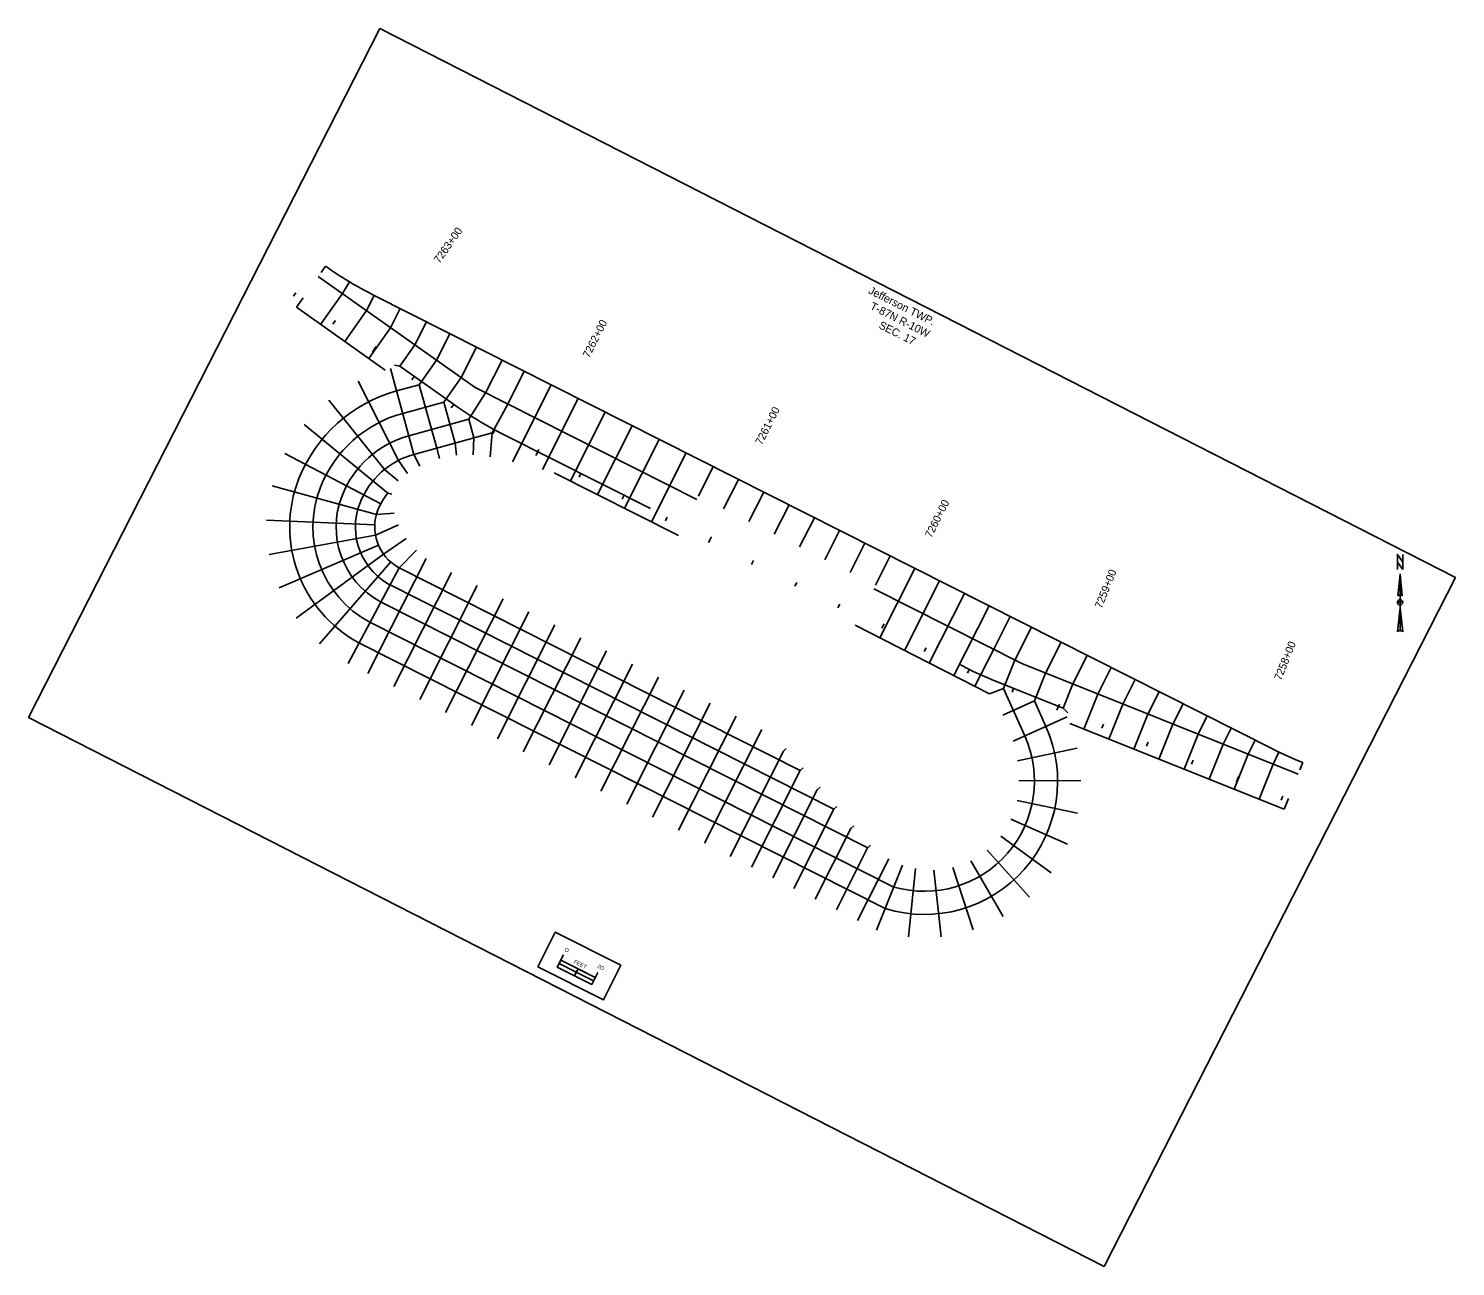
# Model space of a CAD drawing. Extents: x 15558113 to 15568216, y 8783175 to 8787996.
import ezdxf

# ---------------------------------------------------------------- set-up
doc = ezdxf.new("R2010")
doc.units = 0
for name, color, linetype in [('Draft_0', 7, 'Continuous'), ('Drainage', 7, 'Continuous'), ('dsnCellElements', 7, 'Continuous'), ('dsnCellsScaleBlock', 7, 'Continuous'), ('EdgeShoulder', 7, 'Continuous'), ('Miscellanous', 7, 'Continuous'), ('Text', 7, 'Continuous'), ('TextAlignment', 7, 'Continuous')]:
    doc.layers.add(name, color=color, linetype=linetype)

msp = doc.modelspace()

# ---------------------------------------------------------------- linework, layer by layer
at = {"layer": 'Drainage'}
for p, q in [((15558292.1, 8787830.96), (15558290.84, 8787829.17)), ((15558376.44, 8787777.59), (15558375.46, 8787775.64)), ((15558465.72, 8787732.55), (15558464.74, 8787730.6)), ((15558554.45, 8787686.41), (15558555.56, 8787688.6)), ((15558645.85, 8787645.9), (15558645.04, 8787643.87)), ((15558738.67, 8787608.71), (15558737.86, 8787606.68))]:
    msp.add_line(p, q, dxfattribs=at)
at = {"layer": 'dsnCellElements'}
for p, q in [((15558822.58, 8787714.34), (15558823.71, 8787703.08)), ((15558822.58, 8787714.34), (15558822.58, 8787685.05)), ((15558822.58, 8787714.34), (15558823.71, 8787703.08)), ((15558822.58, 8787714.34), (15558822.58, 8787685.05)), ((15558821.46, 8787703.08), (15558821.46, 8787703.08)), ((15558821.46, 8787703.08), (15558821.46, 8787703.08)), ((15558821.5, 8787703.18), (15558821.71, 8787703.42)), ((15558821.5, 8787703.18), (15558821.71, 8787703.42)), ((15558821.18, 8787684.49), (15558822.58, 8787696.88)), ((15558821.18, 8787684.49), (15558822.58, 8787696.88)), ((15558822.58, 8787698.29), (15558822.58, 8787698.29)), ((15558822.58, 8787698.29), (15558822.58, 8787698.29))]:
    msp.add_line(p, q, dxfattribs=at)
for points in [[(15558823.99, 8787716.6), (15558821.18, 8787720.54), (15558821.18, 8787724.48), (15558823.99, 8787720.54)], [(15558823.99, 8787716.6), (15558821.18, 8787720.54), (15558821.18, 8787724.48), (15558823.99, 8787720.54)], [(15558385.47, 8787529.06), (15558419.4, 8787511.95), (15558410.39, 8787494.09), (15558376.46, 8787511.21)]]:
    msp.add_lwpolyline(points, close=True, dxfattribs=at)
for points in [[(15558821.18, 8787716.6), (15558821.18, 8787724.48), (15558823.99, 8787720.54), (15558823.99, 8787724.48)], [(15558821.18, 8787716.6), (15558821.18, 8787724.48), (15558823.99, 8787720.54), (15558823.99, 8787724.48)], [(15558821.46, 8787703.08), (15558822.58, 8787714.34), (15558822.58, 8787703.64)], [(15558821.46, 8787703.08), (15558822.58, 8787714.34), (15558822.58, 8787703.64)], [(15558822.58, 8787698.29), (15558822.58, 8787699.7), (15558821.18, 8787699.7)], [(15558822.58, 8787698.29), (15558822.58, 8787699.7), (15558821.18, 8787699.7)], [(15558823.99, 8787699.7), (15558822.58, 8787699.7), (15558822.58, 8787701.11)], [(15558823.99, 8787699.7), (15558822.58, 8787699.7), (15558822.58, 8787701.11)], [(15558822.58, 8787685.05), (15558822.58, 8787696.88), (15558823.99, 8787684.49)], [(15558822.58, 8787685.05), (15558822.58, 8787696.88), (15558823.99, 8787684.49)]]:
    msp.add_lwpolyline(points, dxfattribs=at)
for centre, radius, start, end in [((15558822.58, 8787699.7), 1.41, 90, 180), ((15558822.58, 8787699.7), 1.41, 90, 180), ((15558822.58, 8787699.7), 1.41, 180, 270), ((15558822.58, 8787699.7), 1.41, 180, 270), ((15558822.58, 8787702.23), 1.41, 90.02039, 143.12574), ((15558822.58, 8787702.23), 1.41, 90.02039, 143.12574), ((15558822.58, 8787702.23), 1.41, 36.84806, 90.02184), ((15558822.58, 8787702.23), 1.41, 36.84806, 90.02184), ((15558822.58, 8787699.7), 1.41, 360, 90), ((15558822.58, 8787699.7), 1.41, 360, 90), ((15558822.58, 8787699.7), 1.41, 270, 360), ((15558822.58, 8787699.7), 1.41, 270, 360), ((15558822.58, 8787683.01), 2.04, 89.98939, 133.61895), ((15558822.58, 8787683.01), 2.04, 89.98939, 133.61895), ((15558822.58, 8787683.01), 2.04, 46.40206, 90.00064), ((15558822.58, 8787683.01), 2.04, 46.40206, 90.00064)]:
    msp.add_arc(centre, radius, start, end, dxfattribs=at)
at = {"layer": 'dsnCellsScaleBlock'}
msp.add_line((15558395.41, 8787506.58), (15558397.21, 8787510.15), dxfattribs=at)
msp.add_line((15558395.41, 8787506.58), (15558397.21, 8787510.15), dxfattribs=at)
for points in [[(15558376.46, 8787511.21), (15558385.47, 8787529.06), (15558419.4, 8787511.95), (15558410.39, 8787494.09)], [(15558386.48, 8787511.08), (15558395.41, 8787506.58), (15558396.32, 8787508.38), (15558387.39, 8787512.88)], [(15558396.32, 8787508.38), (15558405.24, 8787503.87), (15558406.14, 8787505.65), (15558397.21, 8787510.15)]]:
    msp.add_lwpolyline(points, close=True, dxfattribs=at)
for points in [[(15558389.63, 8787517.33), (15558386.48, 8787511.08), (15558404.34, 8787502.07), (15558407.49, 8787508.32)], [(15558388.28, 8787514.65), (15558406.14, 8787505.65)]]:
    msp.add_lwpolyline(points, dxfattribs=at)
at = {"layer": 'EdgeShoulder'}
for p, q in [((15558266.55, 8787873.53), (15558264.24, 8787870.27)), ((15558251.54, 8787852.31), (15558255, 8787857.21)), ((15558291.47, 8787858.55), (15558756.87, 8787623.74)), ((15558251.54, 8787852.31), (15558297.47, 8787819.81)), ((15558384.91, 8787766.75), (15558449.25, 8787734.29)), ((15558610.06, 8787652.43), (15558540.71, 8787687.82)), ((15558762.59, 8787592.66), (15558651.69, 8787637.09)), ((15558772.26, 8787616.79), (15558770.77, 8787613.08)), ((15558762.59, 8787592.66), (15558764.82, 8787598.23))]:
    msp.add_line(p, q, dxfattribs=at)
for centre, start, end in [((15558379.76, 8788033.54), 234.72029, 243.22834), ((15558845.16, 8787798.73), 243.22834, 248.16555)]:
    msp.add_arc(centre, 196, start, end, dxfattribs=at)
at = {"layer": 'Miscellanous'}
msp.add_lwpolyline([(15558669.45, 8787356.2), (15558851.25, 8787712.51), (15558294.69, 8787996.47), (15558112.89, 8787640.17)], close=True, dxfattribs=at)
at = {"layer": 'Text'}
for p, q in [((15558251.28, 8787859.84), (15558250.02, 8787858.05)), ((15558271.69, 8787845.4), (15558270.43, 8787843.61)), ((15558291.39, 8787829.96), (15558292.81, 8787831.96)), ((15558312.51, 8787816.52), (15558311.25, 8787814.74)), ((15558332.92, 8787802.08), (15558331.66, 8787800.3)), ((15558354.15, 8787788.91), (15558353.12, 8787786.99)), ((15558375.89, 8787776.5), (15558376.99, 8787778.69)), ((15558398.76, 8787766.33), (15558397.78, 8787764.38)), ((15558421.08, 8787755.07), (15558420.1, 8787753.12)), ((15558443.4, 8787743.81), (15558442.42, 8787741.86)), ((15558465.17, 8787731.46), (15558466.27, 8787733.64)), ((15558488.04, 8787721.29), (15558487.06, 8787719.34)), ((15558510.36, 8787710.03), (15558509.38, 8787708.08)), ((15558532.68, 8787698.77), (15558531.7, 8787696.82)), ((15558554.45, 8787686.41), (15558555.56, 8787688.6)), ((15558577.32, 8787676.25), (15558576.34, 8787674.3)), ((15558599.65, 8787665), (15558598.69, 8787663.04)), ((15558622.64, 8787655.2), (15558621.83, 8787653.17)), ((15558645.39, 8787644.76), (15558646.3, 8787647.03)), ((15558669.05, 8787636.6), (15558668.24, 8787634.57)), ((15558692.26, 8787627.3), (15558691.45, 8787625.27)), ((15558715.47, 8787618), (15558714.66, 8787615.98)), ((15558738.22, 8787607.57), (15558739.13, 8787609.84)), ((15558761.88, 8787599.41), (15558761.07, 8787597.38))]:
    msp.add_line(p, q, dxfattribs=at)
at = {"layer": 'TextAlignment'}
for p, q in [((15558262.8, 8787868.23), (15558344.07, 8787810.73)), ((15558349.37, 8787808.06), (15558357.92, 8787825.02)), ((15558300.13, 8787820.59), (15558312.33, 8787776.24)), ((15558302.27, 8787822.36), (15558304.94, 8787821.88)), ((15558304.94, 8787821.88), (15558333.22, 8787801.86)), ((15558360.84, 8787802.27), (15558369.4, 8787819.23)), ((15558283.38, 8787814.08), (15558304.34, 8787773.13)), ((15558303.31, 8787809.02), (15558315.07, 8787812.26)), ((15558315.07, 8787812.26), (15558324.09, 8787779.47)), ((15558344.07, 8787810.73), (15558458.62, 8787752.93)), ((15558363.32, 8787772.44), (15558383.37, 8787812.18)), ((15558268.3, 8787804.31), (15558297.14, 8787768.47)), ((15558306.49, 8787797.45), (15558327.74, 8787803.29)), ((15558327.74, 8787803.29), (15558333.57, 8787782.08)), ((15558340.74, 8787794.42), (15558349.37, 8787808.06)), ((15558378.84, 8787768.48), (15558397.34, 8787805.14)), ((15558360.84, 8787802.27), (15558352.8, 8787787.37)), ((15558393.35, 8787762.49), (15558411.3, 8787798.09)), ((15558255.53, 8787791.67), (15558298.76, 8787756.08)), ((15558309.68, 8787785.88), (15558340.74, 8787794.42)), ((15558340.74, 8787794.42), (15558343.39, 8787784.78)), ((15558407.32, 8787755.44), (15558425.27, 8787791.04)), ((15558312.33, 8787776.24), (15558352.8, 8787787.37)), ((15558333.57, 8787782.08), (15558334.27, 8787775.79)), ((15558343.39, 8787784.78), (15558342.98, 8787776.07)), ((15558352.8, 8787787.37), (15558351.79, 8787774.93)), ((15558358.65, 8787786.57), (15558434.74, 8787748.18)), ((15558421.29, 8787748.4), (15558439.24, 8787783.99)), ((15558245.58, 8787776.71), (15558295.15, 8787750.64)), ((15558304.34, 8787773.13), (15558309.04, 8787766.34)), ((15558312.33, 8787776.24), (15558315.42, 8787770.15)), ((15558324.09, 8787779.47), (15558325.59, 8787774.11)), ((15558435.25, 8787741.35), (15558453.21, 8787776.94)), ((15558297.14, 8787768.47), (15558304.18, 8787762.54)), ((15558459.49, 8787754.66), (15558467.18, 8787769.9)), ((15558238.92, 8787760.02), (15558292.9, 8787745.08)), ((15558472.58, 8787748.08), (15558480.26, 8787763.3)), ((15558298.76, 8787756.08), (15558300.92, 8787755.67)), ((15558485.68, 8787741.5), (15558493.35, 8787756.7)), ((15558292.9, 8787745.08), (15558302.01, 8787745.8)), ((15558498.78, 8787734.92), (15558506.43, 8787750.09)), ((15558511.87, 8787728.34), (15558519.51, 8787743.49)), ((15558236.11, 8787742.28), (15558292.05, 8787739.76)), ((15558292.41, 8787734.38), (15558304.26, 8787739.86)), ((15558524.97, 8787721.76), (15558532.6, 8787736.89)), ((15558237.32, 8787724.36), (15558292.41, 8787734.38)), ((15558242.5, 8787707.16), (15558293.97, 8787729.22)), ((15558296.63, 8787724.54), (15558308.34, 8787732.8)), ((15558538.06, 8787715.19), (15558545.68, 8787730.29)), ((15558251.38, 8787691.55), (15558296.63, 8787724.54)), ((15558318.56, 8787722.41), (15558288.54, 8787662.96)), ((15558304.71, 8787717.51), (15558313.62, 8787726.6)), ((15558551.16, 8787708.61), (15558558.77, 8787723.69)), ((15558263.53, 8787678.32), (15558300.28, 8787720.57)), ((15558278.32, 8787668.12), (15558304.71, 8787717.51)), ((15558331.68, 8787715.11), (15558301.93, 8787656.2)), ((15558512.22, 8787612.76), (15558304.31, 8787717.74)), ((15558553.43, 8787681.32), (15558571.55, 8787717.24)), ((15558529.66, 8787592.75), (15558299.63, 8787708.9)), ((15558345.07, 8787708.35), (15558315.32, 8787649.44)), ((15558626.92, 8787668.03), (15558550.21, 8787706.73)), ((15558566.19, 8787674.82), (15558584.34, 8787710.79)), ((15558547.1, 8787572.74), (15558294.97, 8787700.04)), ((15558358.46, 8787701.59), (15558328.71, 8787642.68)), ((15558578.94, 8787668.31), (15558597.12, 8787704.34)), ((15558371.85, 8787694.83), (15558342.1, 8787635.92)), ((15558591.7, 8787661.8), (15558609.91, 8787697.89)), ((15558612.3, 8787675.4), (15558620.86, 8787692.36)), ((15558560.65, 8787552.46), (15558289.41, 8787689.41)), ((15558385.24, 8787688.07), (15558355.49, 8787629.16)), ((15558623.25, 8787669.87), (15558631.81, 8787686.84)), ((15558556.21, 8787541.26), (15558283.86, 8787678.77)), ((15558398.63, 8787681.31), (15558368.88, 8787622.39)), ((15558639.16, 8787663.12), (15558647.21, 8787679.07)), ((15558412.02, 8787674.55), (15558382.27, 8787615.63)), ((15558612.3, 8787675.4), (15558602.54, 8787656.27)), ((15558617.36, 8787655.16), (15558623.25, 8787669.87)), ((15558653.28, 8787657.46), (15558660.73, 8787672.25)), ((15558425.41, 8787667.79), (15558395.66, 8787608.87)), ((15558597.48, 8787666.08), (15558595.07, 8787667.29)), ((15558769.84, 8787610.76), (15558626.92, 8787668.03)), ((15558633.4, 8787648.73), (15558639.16, 8787663.12)), ((15558666.23, 8787652.28), (15558673.15, 8787665.98)), ((15558438.8, 8787661.03), (15558409.05, 8787602.11)), ((15558617.36, 8787655.16), (15558610.06, 8787652.43)), ((15558648.26, 8787644.93), (15558613.18, 8787658.99)), ((15558628.39, 8787630.59), (15558617.36, 8787655.16)), ((15558648.26, 8787644.93), (15558653.28, 8787657.46)), ((15558679.18, 8787647.09), (15558685.56, 8787659.72)), ((15558452.19, 8787654.27), (15558422.44, 8787595.35)), ((15558465.58, 8787647.51), (15558435.83, 8787588.59)), ((15558633.4, 8787648.73), (15558617.01, 8787641.38)), ((15558639.34, 8787635.5), (15558633.4, 8787648.73)), ((15558658.98, 8787634.17), (15558666.23, 8787652.28)), ((15558692.13, 8787641.9), (15558697.97, 8787653.46)), ((15558478.97, 8787640.75), (15558449.22, 8787581.83)), ((15558622.36, 8787627.88), (15558650.28, 8787640.42)), ((15558650.67, 8787642.62), (15558648.26, 8787644.93)), ((15558671.93, 8787628.98), (15558679.18, 8787647.09)), ((15558684.88, 8787623.8), (15558692.13, 8787641.9)), ((15558705.08, 8787636.71), (15558710.38, 8787647.2)), ((15558718.04, 8787631.52), (15558722.79, 8787640.94)), ((15558492.36, 8787633.99), (15558462.61, 8787575.07)), ((15558697.83, 8787618.61), (15558705.08, 8787636.71)), ((15558730.99, 8787626.33), (15558735.2, 8787634.68)), ((15558710.78, 8787613.42), (15558718.04, 8787631.52)), ((15558723.74, 8787608.23), (15558730.99, 8787626.33)), ((15558743.94, 8787621.14), (15558747.61, 8787628.42)), ((15558503.5, 8787622.77), (15558476, 8787568.31)), ((15558503.5, 8787622.77), (15558505, 8787624.08)), ((15558624.55, 8787617.64), (15558655.57, 8787624.33)), ((15558736.69, 8787603.04), (15558743.94, 8787621.14)), ((15558756.89, 8787615.95), (15558759.93, 8787622.24)), ((15558512.22, 8787612.76), (15558486.98, 8787562.77)), ((15558512.22, 8787612.76), (15558513.72, 8787614.08)), ((15558749.64, 8787597.85), (15558756.89, 8787615.95)), ((15558520.94, 8787602.76), (15558522.45, 8787604.07)), ((15558625.35, 8787607.4), (15558657.39, 8787607.5)), ((15558520.94, 8787602.76), (15558497.95, 8787557.23)), ((15558624.37, 8787597.21), (15558655.67, 8787590.66)), ((15558529.66, 8787592.75), (15558508.93, 8787551.69)), ((15558529.66, 8787592.75), (15558531.17, 8787594.07)), ((15558538.38, 8787582.75), (15558519.9, 8787546.15)), ((15558538.38, 8787582.75), (15558539.89, 8787584.06)), ((15558621.2, 8787587.47), (15558650.5, 8787574.55)), ((15558547.1, 8787572.74), (15558548.61, 8787574.06)), ((15558615.93, 8787578.72), (15558642.08, 8787559.86)), ((15558547.08, 8787572.7), (15558530.9, 8787540.65)), ((15558558.01, 8787567.07), (15558541.85, 8787535.07)), ((15558608.87, 8787571.43), (15558630.8, 8787547.24)), ((15558565.2, 8787563.77), (15558551.68, 8787530.1)), ((15558571.81, 8787561.97), (15558568.23, 8787526.65)), ((15558581.41, 8787561.19), (15558585.16, 8787526.72)), ((15558591.11, 8787562.5), (15558601.7, 8787530.3)), ((15558600.43, 8787565.94), (15558617.14, 8787537.24))]:
    msp.add_line(p, q, dxfattribs=at)
for points in [[(15558264.02, 8787843.48), (15558275.28, 8787859.39), (15558278.92, 8787865.46)], [(15558276.5, 8787834.64), (15558287.77, 8787850.56), (15558291.73, 8787858.41)], [(15558288.99, 8787825.81), (15558300.25, 8787841.73), (15558305.23, 8787851.6)], [(15558304.94, 8787821.88), (15558312.74, 8787832.9), (15558318.74, 8787844.79)], [(15558315.07, 8787812.26), (15558324.03, 8787824.91), (15558330.95, 8787838.63)], [(15558327.74, 8787803.29), (15558336.69, 8787815.95), (15558344.65, 8787831.72)]]:
    msp.add_lwpolyline(points, dxfattribs=at)
for centre, radius, start, end in [((15558323.47, 8787735.74), 76, 105.37857, 158.4451), ((15558323.47, 8787735.74), 64, 105.37857, 158.4451), ((15558448.74, 8787965.13), 200, 234.72029, 243.22834), ((15558323.47, 8787735.74), 52, 105.37857, 158.4451), ((15558323.47, 8787735.74), 42, 105.37857, 158.4451), ((15558316.03, 8787738.68), 68, 158.4451, 241.76625), ((15558316.03, 8787738.68), 56, 158.4451, 241.61901), ((15558316.03, 8787738.68), 44, 158.4451, 241.41504), ((15558316.03, 8787738.68), 34, 158.4451, 245.25302), ((15558323.47, 8787735.74), 32, 140.53735, 158.4451), ((15558316.03, 8787738.68), 24, 158.4451, 240.77935), ((15558687.57, 8787844.64), 200, 243.22834, 248.16555), ((15558576.39, 8787607.24), 69, 252.99291, 24.17605), ((15558576.39, 8787607.24), 57, 253.97625, 24.17605)]:
    msp.add_arc(centre, radius, start, end, dxfattribs=at)

# ---------------------------------------------------------------- texts
at = {"layer": 'Draft_0'}
for s, p in [('Jefferson TWP.', (15558547.11, 8787859.65)), ('T-87N R-10W', (15558547.94, 8787851.61)), ('SEC. 17', (15558552.44, 8787841.73))]:
    msp.add_text(s, height=4.08, rotation=333.22834, dxfattribs=at).set_placement(p)
at = {"layer": 'dsnCellsScaleBlock'}
for s, p in [('O', (15558389.95, 8787519.41)), ('FEET', (15558394.73, 8787513.2)), ('2O', (15558406.94, 8787510.84))]:
    msp.add_text(s, height=2, rotation=333.22834, dxfattribs=at).set_placement(p)
at = {"layer": 'Text'}
for s, rotation, p in [('7263+00', 54.72029, (15558325.5, 8787874.7)), ('7262+00', 63.22834, (15558403.01, 8787825.8)), ('7261+00', 63.22834, (15558492.29, 8787780.75)), ('7260+00', 63.22834, (15558580.06, 8787732.72)), ('7259+00', 68.16555, (15558668.16, 8787696.21)), ('7258+00', 68.16555, (15558760.99, 8787659.01))]:
    msp.add_text(s, height=4.008, rotation=rotation, dxfattribs=at).set_placement(p)

doc.saveas('drawing.dxf')
